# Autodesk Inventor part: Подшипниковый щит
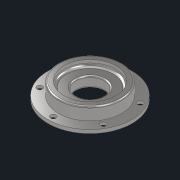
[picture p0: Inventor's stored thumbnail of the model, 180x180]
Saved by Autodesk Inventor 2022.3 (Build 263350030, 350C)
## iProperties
Created: 2022-08
Part Number: Подшипниковый щит
Material: Сталь 40ХНМА
Document SubType Name: Modeling
Designer: Карташов
Density: 7.85 g/cm^3
Appearance: С умеренной полировкой
Author: Карташов
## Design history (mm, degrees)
sketch "Эскиз1"
  geometry: L1 (0, 0)-(0, 34.001); L2 (22, 0)-(60, 0); L3 (60, 0)-(60, 5); L4 (60, 5)-(45, 5); L5 (45, 5)-(45, 21); L6 (43, 23)-(37, 23); L7 (37, 23)-(37, 18.76); L8 (33, 14.76)-(22, 14.76); L9 (20, 12.76)-(20, 2); A1 r 4 centre (33, 18.76) between (33, 14.76) and (37, 18.76); A2 r 2 centre (22, 12.76) between (22, 14.76) and (20, 12.76); A3 r 2 centre (22, 2) between (20, 2) and (22, 0); A4 r 2 centre (43, 21) between (45, 21) and (43, 23); 2 further points
  constraints: 18 end point, 8 point on circle, 8 tangent, 4 centre point, 4 horizontal, 4 vertical, 2 equal radius, 2 point on line, 1 horizontal alignment, 1 midpoint, 1 perpendicular
  dimensions: "d0" = 90 diameter of L5 point (0, 17); "d1" = 120 diameter of L3 L1; "d2" = 40 diameter of L9 L1; "d3" = 23 vertical distance of L2.end point (45, 23); "d4" = 5 distance of L2.end L3.end; "d5" = 8.24 distance between parallel lines of L8 L6; "d6" = 8 distance of point (45, 23) L6.end; "d7" = 4 radius of A1; "d8" = 2 radius of A2
revolve "Вращение1" sketch "Эскиз1" stored, may be unused: angle "d9" = 90 deg
sketch "Эскиз2"
  geometry: C1 r 45 at (0, 0) reference; C2 r 60 at (0, 0) reference; 2 further points
  constraints: 1 vertical alignment
  dimensions: "d10" = 52.5 distance of point (0, 0) point (0, -52.5)
  node "Спроецированная петля1"
sketch "Эскиз3"
  geometry: 2 further points
hole "Отверстие1" sketch "Эскиз3" at (0, 52.5) diameter "d11" = 8; stored, may be unused: countersink angle "d15" = 90 deg, drill point angle "d17" = 0 deg; dims "d12" = 6, "d13" = 13, "d14" = 1, "d16" = 22.5
pattern_circular "Круговой массив1" dims angle "d19" = 360 deg
node "Твердое тело1"
